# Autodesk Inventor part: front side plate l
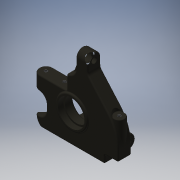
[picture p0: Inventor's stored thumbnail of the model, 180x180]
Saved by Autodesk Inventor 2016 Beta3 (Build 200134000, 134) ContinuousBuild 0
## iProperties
Shininess: 41.0
Compacted: True
Length Units: 11272
Angle Units: 11279
Time Units: 11290
Mass Units: 11286
Length Display Precision: 3
Angle Display Precision: 2
Company: Autodesk
Created: 2001-02
Part Number: front side plate l
Document SubType Name: Modeling
Designer: Autodesk, Inc.
Material: Stiffzel
Project: Inventor Samples
Density: 1.28 g/cm^3
Stock Number: front side plate l
Mass: 15.7207 g
Surface Area: 55.8097 cm^2
Volume: 12.2818 cm^3
Appearance: Stiffzel
Density: 0.0
Volumn: 0.0
Area: 0.0
PropertySet Name: Model Information
Control State: 0
Master: False
Checked Out: False
Author: Autodesk, Inc.
Revision Number: A
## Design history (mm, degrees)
node "front side plate r" dims "d3" = 10
body "Solid1"
tag "TaggingFeature2"
feature "DerivedBody::front side plate r" dims "d3" = 10
